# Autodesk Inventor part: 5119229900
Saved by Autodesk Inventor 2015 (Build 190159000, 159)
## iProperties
Created: 2020-07
Part Number: 5119229900
Checked By: TraceParts S.A.
Material: Generic
Catalog Web Link: www.traceparts.com
Document SubType Name: Modeling
Designer: TraceParts
Density: 1 g/cm^3
Appearance: Default
Company: TraceParts S.A.
Author: TraceParts
REFERENCE: 5119229900
DESIGN: HIB-1000 P 0,55KW (230V 50HZ) - 5119229900
SUPPLIER: Soler & Palau
TraceParts.PartNumber: 10-20122018-119595
TraceParts.PartTitle: HIB-P/HIT-P
TraceParts.InstanceId: 10-20122018-119595AQSXCPV71XYCIWLLAJ360J46I
TraceParts.PartStatus: Published
TraceParts.PartVersion: 1.0.2
TRACEPARTS: TRACEPARTS
TraceParts.PartLanguage: en
TraceParts.ClassPath: SOLER_PALAU:10-20122018-119595
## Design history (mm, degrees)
feature "5119229900"
body "Solid1"
